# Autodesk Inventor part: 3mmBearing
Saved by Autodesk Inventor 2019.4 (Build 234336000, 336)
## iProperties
Created: 2020-02
Part Number: 3mmBearing
Material: Generic
Document SubType Name: Modeling
Designer: Administrator
Density: 1 g/cm^3
Appearance: Default
Title: 3mmBearing v2
Author: Administrator
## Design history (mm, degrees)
feature "Body1"
body "Solid1"
